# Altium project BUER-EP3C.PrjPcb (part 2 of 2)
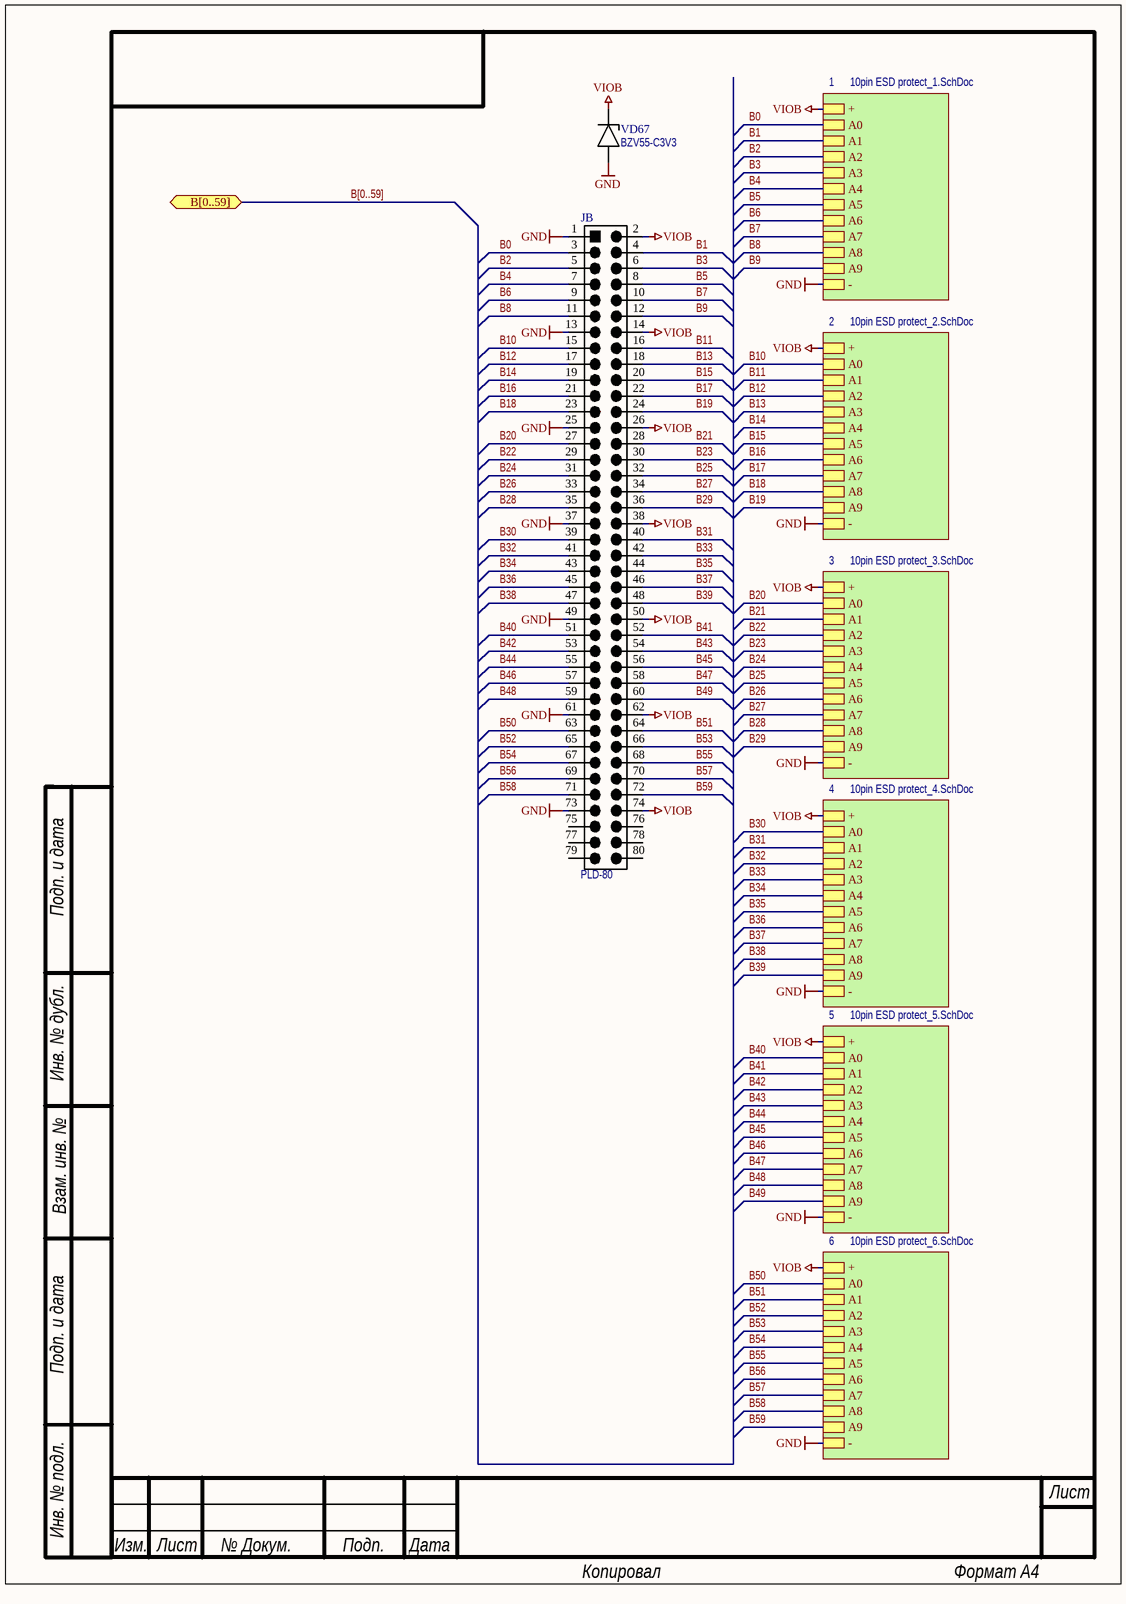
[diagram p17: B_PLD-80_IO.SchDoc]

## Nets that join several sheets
1.2V: Power (53 pins), 5V_to_1.2V_stepdown (C34.1 C35.1 L1.2 R6.2)
1.8V: Power (PA.3 PB.3), 5V_to_1.8V_stepdown (C43.1 C44.1 L2.2 R17.2)
2.5V: Power (12 pins), 5V_to_2.5V_stepdown (C52.1 C53.1 L4.2 R8.2)
3.3V: Main (21 pins), FPGA1 (R3.2), Power (8 pins), 5V_to_3.3V_stepdown (C55.1 C56.1 L5.2 R10.2), FPGA2 (R19.2)
GND: Main (36 pins), FPGA1 (14 pins), Power (108 pins), 5V_to_1.2V_stepdown (6 pins), 5V_to_2.5V_stepdown (6 pins), 5V_to_3.3V_stepdown (6 pins), 5A Stepdown 5V (14 pins), 5V_to_1.8V_stepdown (6 pins), FPGA2 (6 pins), A_PLD-80_IO (8 pins), A/1 (11 pins), A/2 (11 pins), A/3 (11 pins), A/4 (11 pins), A/6 (11 pins), A/5 (11 pins), B_PLD-80_IO (8 pins), B/1 (11 pins), B/2 (11 pins), B/3 (11 pins), B/4 (11 pins), B/6 (11 pins), B/5 (11 pins)
POWER: Power (5 pins), 5A Stepdown 5V (C66.1 C67.1 DA4.7)
VCC: 5V_to_1.2V_stepdown (C33.1 DA1.4 DA1.5 DA1.6), 5V_to_2.5V_stepdown (C51.1 DA2.4 DA2.5 DA2.6), 5V_to_3.3V_stepdown (C54.1 DA3.4 DA3.5 DA3.6), 5A Stepdown 5V (7 pins), 5V_to_1.8V_stepdown (C42.1 DA5.4 DA5.5 DA5.6)
VIOA: Power (29 pins), A_PLD-80_IO (8 pins), A/1 (11 pins), A/2 (11 pins), A/3 (11 pins), A/4 (11 pins), A/6 (11 pins), A/5 (11 pins)
VIOB: Power (28 pins), B_PLD-80_IO (8 pins), B/1 (11 pins), B/2 (11 pins), B/3 (11 pins), B/4 (11 pins), B/6 (11 pins), B/5 (11 pins)
A0: FPGA1 (DD1.37), FPGA2 (DD3.28), A_PLD-80_IO (JA.3), A/1 (VD15A.3)
A1: FPGA1 (DD1.38), FPGA2 (DD3.30), A_PLD-80_IO (JA.4), A/1 (VD14A.3)
A2: FPGA1 (DD1.39), FPGA2 (DD3.31), A_PLD-80_IO (JA.5), A/1 (VD13A.3)
A3: FPGA1 (DD1.41), FPGA2 (DD3.32), A_PLD-80_IO (JA.6), A/1 (VD12A.3)
A4: FPGA1 (DD1.43), FPGA2 (DD3.33), A_PLD-80_IO (JA.7), A/1 (VD11A.3)
A5: FPGA1 (DD1.44), FPGA2 (DD3.34), A_PLD-80_IO (JA.8), A/1 (VD10A.3)
A6: FPGA1 (DD1.45), FPGA2 (DD3.38), A_PLD-80_IO (JA.9), A/1 (VD9A.3)
A7: FPGA1 (DD1.46), FPGA2 (DD3.39), A_PLD-80_IO (JA.10), A/1 (VD8A.3)
A8: FPGA1 (DD1.49), FPGA2 (DD3.42), A_PLD-80_IO (JA.11), A/1 (VD7A.3)
A9: FPGA1 (DD1.50), FPGA2 (DD3.43), A_PLD-80_IO (JA.12), A/1 (VD6A.3)
A10: FPGA1 (DD1.51), A_PLD-80_IO (JA.15), A/2 (VD25A.3)
A11: FPGA1 (DD1.52), A_PLD-80_IO (JA.16), A/2 (VD24A.3)
A12: FPGA1 (DD1.55), A_PLD-80_IO (JA.17), A/2 (VD23A.3)
A13: FPGA1 (DD1.56), A_PLD-80_IO (JA.18), A/2 (VD22A.3)
A14: FPGA1 (DD1.57), A_PLD-80_IO (JA.19), A/2 (VD21A.3)
A15: FPGA1 (DD1.63), A_PLD-80_IO (JA.20), A/2 (VD20A.3)
A16: FPGA1 (DD1.64), A_PLD-80_IO (JA.21), A/2 (VD19A.3)
A17: FPGA1 (DD1.65), A_PLD-80_IO (JA.22), A/2 (VD18A.3)
A18: FPGA1 (DD1.68), A_PLD-80_IO (JA.23), A/2 (VD17A.3)
A19: FPGA1 (DD1.69), A_PLD-80_IO (JA.24), A/2 (VD16A.3)
A20: FPGA1 (DD1.70), FPGA2 (DD3.44), A_PLD-80_IO (JA.27), A/3 (VD35A.3)
A21: FPGA1 (DD1.71), FPGA2 (DD3.46), A_PLD-80_IO (JA.28), A/3 (VD34A.3)
A22: FPGA1 (DD1.72), FPGA2 (DD3.49), A_PLD-80_IO (JA.29), A/3 (VD33A.3)
A23: FPGA1 (DD1.73), FPGA2 (DD3.50), A_PLD-80_IO (JA.30), A/3 (VD32A.3)
A24: FPGA1 (DD1.76), FPGA2 (DD3.51), A_PLD-80_IO (JA.31), A/3 (VD31A.3)
A25: FPGA1 (DD1.78), FPGA2 (DD3.52), A_PLD-80_IO (JA.32), A/3 (VD30A.3)
A26: FPGA1 (DD1.80), FPGA2 (DD3.53), A_PLD-80_IO (JA.33), A/3 (VD29A.3)
A27: FPGA1 (DD1.81), FPGA2 (DD3.54), A_PLD-80_IO (JA.34), A/3 (VD28A.3)
A28: FPGA1 (DD1.82), FPGA2 (DD3.55), A_PLD-80_IO (JA.35), A/3 (VD27A.3)
A29: FPGA1 (DD1.83), FPGA2 (DD3.58), A_PLD-80_IO (JA.36), A/3 (VD26A.3)
A30: FPGA1 (DD1.84), FPGA2 (DD3.59), A_PLD-80_IO (JA.39), A/4 (VD45A.3)
A31: FPGA1 (DD1.85), FPGA2 (DD3.60), A_PLD-80_IO (JA.40), A/4 (VD44A.3)
A32: FPGA1 (DD1.86), FPGA2 (DD3.64), A_PLD-80_IO (JA.41), A/4 (VD43A.3)
A33: FPGA1 (DD1.87), FPGA2 (DD3.65), A_PLD-80_IO (JA.42), A/4 (VD42A.3)
A34: FPGA1 (DD1.88), FPGA2 (DD3.66), A_PLD-80_IO (JA.43), A/4 (VD41A.3)
A35: FPGA1 (DD1.126), FPGA2 (DD3.67), A_PLD-80_IO (JA.44), A/4 (VD40A.3)
A36: FPGA1 (DD1.127), FPGA2 (DD3.68), A_PLD-80_IO (JA.45), A/4 (VD39A.3)
A37: FPGA1 (DD1.128), FPGA2 (DD3.69), A_PLD-80_IO (JA.46), A/4 (VD38A.3)
A38: FPGA1 (DD1.131), FPGA2 (DD3.70), A_PLD-80_IO (JA.47), A/4 (VD37A.3)
A39: FPGA1 (DD1.132), FPGA2 (DD3.71), A_PLD-80_IO (JA.48), A/4 (VD36A.3)
A40: FPGA1 (DD1.133), FPGA2 (DD3.72), A_PLD-80_IO (JA.51), A/5 (VD55A.3)
A41: FPGA1 (DD1.134), A_PLD-80_IO (JA.52), A/5 (VD54A.3)
A42: FPGA1 (DD1.135), A_PLD-80_IO (JA.53), A/5 (VD53A.3)
A43: FPGA1 (DD1.137), A_PLD-80_IO (JA.54), A/5 (VD52A.3)
A44: FPGA1 (DD1.139), A_PLD-80_IO (JA.55), A/5 (VD51A.3)
A45: FPGA1 (DD1.142), A_PLD-80_IO (JA.56), A/5 (VD50A.3)
A46: FPGA1 (DD1.143), A_PLD-80_IO (JA.57), A/5 (VD49A.3)
A47: FPGA1 (DD1.145), A_PLD-80_IO (JA.58), A/5 (VD48A.3)
A48: FPGA1 (DD1.146), A_PLD-80_IO (JA.59), A/5 (VD47A.3)
A49: FPGA1 (DD1.147), A_PLD-80_IO (JA.60), A/5 (VD46A.3)
A50: FPGA1 (DD1.148), A_PLD-80_IO (JA.63), A/6 (VD65A.3)
A51: FPGA1 (DD1.159), A_PLD-80_IO (JA.64), A/6 (VD64A.3)
A52: FPGA1 (DD1.160), A_PLD-80_IO (JA.65), A/6 (VD63A.3)
A53: FPGA1 (DD1.161), A_PLD-80_IO (JA.66), A/6 (VD62A.3)
A54: FPGA1 (DD1.162), A_PLD-80_IO (JA.67), A/6 (VD61A.3)
A55: FPGA1 (DD1.164), A_PLD-80_IO (JA.68), A/6 (VD60A.3)
A56: FPGA1 (DD1.166), A_PLD-80_IO (JA.69), A/6 (VD59A.3)
A57: FPGA1 (DD1.167), A_PLD-80_IO (JA.70), A/6 (VD58A.3)
A58: FPGA1 (DD1.168), A_PLD-80_IO (JA.71), A/6 (VD57A.3)
A59: FPGA1 (DD1.169), A_PLD-80_IO (JA.72), A/6 (VD56A.3)
ASD: Main (DD2.15 X2.9), FPGA1 (DD1.12), FPGA2 (DD3.6)
B0: FPGA1 (DD1.93), FPGA2 (DD3.73), B_PLD-80_IO (JB.3), B/1 (VD15B.3)
B1: FPGA1 (DD1.94), FPGA2 (DD3.74), B_PLD-80_IO (JB.4), B/1 (VD14B.3)
B2: FPGA1 (DD1.95), FPGA2 (DD3.75), B_PLD-80_IO (JB.5), B/1 (VD13B.3)
B3: FPGA1 (DD1.98), FPGA2 (DD3.76), B_PLD-80_IO (JB.6), B/1 (VD12B.3)
B4: FPGA1 (DD1.99), FPGA2 (DD3.77), B_PLD-80_IO (JB.7), B/1 (VD11B.3)
B5: FPGA1 (DD1.100), FPGA2 (DD3.79), B_PLD-80_IO (JB.8), B/1 (VD10B.3)
B6: FPGA1 (DD1.101), FPGA2 (DD3.80), B_PLD-80_IO (JB.9), B/1 (VD9B.3)
B7: FPGA1 (DD1.102), FPGA2 (DD3.83), B_PLD-80_IO (JB.10), B/1 (VD8B.3)
B8: FPGA1 (DD1.103), FPGA2 (DD3.84), B_PLD-80_IO (JB.11), B/1 (VD7B.3)
B9: FPGA1 (DD1.106), FPGA2 (DD3.85), B_PLD-80_IO (JB.12), B/1 (VD6B.3)
B10: FPGA1 (DD1.107), FPGA2 (DD3.86), B_PLD-80_IO (JB.15), B/2 (VD25B.3)
B11: FPGA1 (DD1.108), FPGA2 (DD3.87), B_PLD-80_IO (JB.16), B/2 (VD24B.3)
B12: FPGA1 (DD1.109), B_PLD-80_IO (JB.17), B/2 (VD23B.3)
B13: FPGA1 (DD1.110), B_PLD-80_IO (JB.18), B/2 (VD22B.3)
B14: FPGA1 (DD1.111), FPGA2 (DD3.98), B_PLD-80_IO (JB.19), B/2 (VD21B.3)
B15: FPGA1 (DD1.112), FPGA2 (DD3.99), B_PLD-80_IO (JB.20), B/2 (VD20B.3)
B16: FPGA1 (DD1.113), FPGA2 (DD3.100), B_PLD-80_IO (JB.21), B/2 (VD19B.3)
B17: FPGA1 (DD1.114), FPGA2 (DD3.101), B_PLD-80_IO (JB.22), B/2 (VD18B.3)
B18: FPGA1 (DD1.117), FPGA2 (DD3.103), B_PLD-80_IO (JB.23), B/2 (VD17B.3)
B19: FPGA1 (DD1.118), FPGA2 (DD3.104), B_PLD-80_IO (JB.24), B/2 (VD16B.3)
B20: FPGA1 (DD1.119), B_PLD-80_IO (JB.27), B/3 (VD35B.3)
B21: FPGA1 (DD1.120), B_PLD-80_IO (JB.28), B/3 (VD34B.3)
B22: FPGA1 (DD1.181), B_PLD-80_IO (JB.29), B/3 (VD33B.3)
B23: FPGA1 (DD1.182), B_PLD-80_IO (JB.30), B/3 (VD32B.3)
B24: FPGA1 (DD1.183), B_PLD-80_IO (JB.31), B/3 (VD31B.3)
B25: FPGA1 (DD1.184), B_PLD-80_IO (JB.32), B/3 (VD30B.3)
B26: FPGA1 (DD1.185), B_PLD-80_IO (JB.33), B/3 (VD29B.3)
B27: FPGA1 (DD1.186), B_PLD-80_IO (JB.34), B/3 (VD28B.3)
B28: FPGA1 (DD1.187), B_PLD-80_IO (JB.35), B/3 (VD27B.3)
B29: FPGA1 (DD1.188), B_PLD-80_IO (JB.36), B/3 (VD26B.3)
B30: FPGA1 (DD1.189), FPGA2 (DD3.105), B_PLD-80_IO (JB.39), B/4 (VD45B.3)
B31: FPGA1 (DD1.194), FPGA2 (DD3.106), B_PLD-80_IO (JB.40), B/4 (VD44B.3)
B32: FPGA1 (DD1.195), FPGA2 (DD3.110), B_PLD-80_IO (JB.41), B/4 (VD43B.3)
B33: FPGA1 (DD1.196), FPGA2 (DD3.111), B_PLD-80_IO (JB.42), B/4 (VD42B.3)
B34: FPGA1 (DD1.197), FPGA2 (DD3.112), B_PLD-80_IO (JB.43), B/4 (VD41B.3)
B35: FPGA1 (DD1.198), FPGA2 (DD3.113), B_PLD-80_IO (JB.44), B/4 (VD40B.3)
B36: FPGA1 (DD1.199), FPGA2 (DD3.114), B_PLD-80_IO (JB.45), B/4 (VD39B.3)
B37: FPGA1 (DD1.200), FPGA2 (DD3.115), B_PLD-80_IO (JB.46), B/4 (VD38B.3)
B38: FPGA1 (DD1.201), FPGA2 (DD3.119), B_PLD-80_IO (JB.47), B/4 (VD37B.3)
B39: FPGA1 (DD1.202), FPGA2 (DD3.120), B_PLD-80_IO (JB.48), B/4 (VD36B.3)
B40: FPGA1 (DD1.203), FPGA2 (DD3.121), B_PLD-80_IO (JB.51), B/5 (VD55B.3)
B41: FPGA1 (DD1.207), FPGA2 (DD3.124), B_PLD-80_IO (JB.52), B/5 (VD54B.3)
B42: FPGA1 (DD1.214), FPGA2 (DD3.125), B_PLD-80_IO (JB.53), B/5 (VD53B.3)
B43: FPGA1 (DD1.216), FPGA2 (DD3.126), B_PLD-80_IO (JB.54), B/5 (VD52B.3)
B44: FPGA1 (DD1.217), FPGA2 (DD3.127), B_PLD-80_IO (JB.55), B/5 (VD51B.3)
B45: FPGA1 (DD1.218), B_PLD-80_IO (JB.56), B/5 (VD50B.3)
B46: FPGA1 (DD1.219), B_PLD-80_IO (JB.57), B/5 (VD49B.3)
B47: FPGA1 (DD1.220), B_PLD-80_IO (JB.58), B/5 (VD48B.3)
B48: FPGA1 (DD1.221), FPGA2 (DD3.128), B_PLD-80_IO (JB.59), B/5 (VD47B.3)
B49: FPGA1 (DD1.222), FPGA2 (DD3.129), B_PLD-80_IO (JB.60), B/5 (VD46B.3)
B50: FPGA1 (DD1.223), FPGA2 (DD3.132), B_PLD-80_IO (JB.63), B/6 (VD65B.3)
B51: FPGA1 (DD1.224), FPGA2 (DD3.133), B_PLD-80_IO (JB.64), B/6 (VD64B.3)
B52: FPGA1 (DD1.226), FPGA2 (DD3.135), B_PLD-80_IO (JB.65), B/6 (VD63B.3)
B53: FPGA1 (DD1.230), FPGA2 (DD3.136), B_PLD-80_IO (JB.66), B/6 (VD62B.3)
B54: FPGA1 (DD1.231), FPGA2 (DD3.137), B_PLD-80_IO (JB.67), B/6 (VD61B.3)
B55: FPGA1 (DD1.232), FPGA2 (DD3.138), B_PLD-80_IO (JB.68), B/6 (VD60B.3)
B56: FPGA1 (DD1.233), FPGA2 (DD3.141), B_PLD-80_IO (JB.69), B/6 (VD59B.3)
B57: FPGA1 (DD1.234), FPGA2 (DD3.142), B_PLD-80_IO (JB.70), B/6 (VD58B.3)
B58: FPGA1 (DD1.235), FPGA2 (DD3.143), B_PLD-80_IO (JB.71), B/6 (VD57B.3)
B59: FPGA1 (DD1.236), FPGA2 (DD3.144), B_PLD-80_IO (JB.72), B/6 (VD56B.3)
BUT0: Main (5 pins), FPGA1 (DD1.19), FPGA2 (DD3.1)
BUT1: Main (C91.1 K2.2 R21.1), FPGA1 (DD1.20), FPGA2 (DD3.2)
BUT2: Main (C92.1 K3.2 R22.1), FPGA1 (DD1.21), FPGA2 (DD3.3)
BUT3: Main (C93.1 K4.2 R23.1), FPGA1 (DD1.22), FPGA2 (DD3.4)
CLK0: Main (ZQ1.3), FPGA1 (DD1.31), FPGA2 (DD3.22)
CLK1: Main (DD13.4), FPGA1 (DD1.149), FPGA2 (DD3.88)
CONFIG_DONE: Main (R14.1 X2.3), FPGA1 (DD1.153), FPGA2 (DD3.92)
DATA: Main (DD2.8 X2.7), FPGA1 (DD1.24), FPGA2 (DD3.13)
DCLK: Main (DD2.16 X2.1), FPGA1 (DD1.23), FPGA2 (DD3.12)
JTAG.TCK: Main (R4.1 X1.1), FPGA1 (DD1.27), FPGA2 (DD3.16)
JTAG.TDI: Main (R1.1 X1.9), FPGA1 (DD1.26), FPGA2 (DD3.15)
JTAG.TDO: Main (X1.3), FPGA1 (DD1.29), FPGA2 (DD3.20)
JTAG.TMS: Main (R2.1 X1.5), FPGA1 (DD1.28), FPGA2 (DD3.18)
LED0: Main (R24.2), FPGA1 (DD1.18), FPGA2 (DD3.11)
LED1: Main (R25.2), FPGA1 (DD1.13), FPGA2 (DD3.10)
LED2: Main (R26.2), FPGA1 (DD1.9), FPGA2 (DD3.7)
LED3: Main (R27.2), FPGA1 (DD1.6)
LED4: Main (R28.2), FPGA1 (DD1.5)
LED5: Main (R29.2), FPGA1 (DD1.4)
MSEL0: Main (R5.1 S1.8), FPGA1 (DD1.155), FPGA2 (DD3.94)
MSEL1: Main (R5.2 S1.7), FPGA1 (DD1.157), FPGA2 (DD3.96)
MSEL2: Main (R5.3 S1.6), FPGA1 (DD1.158), FPGA2 (DD3.97)
nCE: Main (R16.2 X2.6), FPGA1 (DD1.30), FPGA2 (DD3.21)
nCONFIG: Main (R15.1 X2.5), FPGA1 (DD1.25), FPGA2 (DD3.14)
nCS: Main (DD2.7 X2.8), FPGA1 (DD1.14), FPGA2 (DD3.8)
